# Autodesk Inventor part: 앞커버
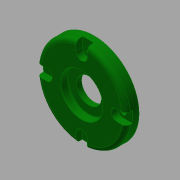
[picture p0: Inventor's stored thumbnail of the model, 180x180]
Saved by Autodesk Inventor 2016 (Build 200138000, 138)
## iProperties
Created: 2019-01
Part Number: 앞커버
Material: 알루미늄 6061
Document SubType Name: Modeling
Designer: mduedu
Density: 2.71 g/cm^3
Appearance: 진녹색
Mass: 65.0159 g
Surface Area: 90.7546 cm^2
Volume: 23.9911 cm^3
Author: mduedu
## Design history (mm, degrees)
sketch "스케치1"
  geometry: L1 (0, 0)-(9, 0); L2 (9, 0)-(9, 32); L3 (9, 32)-(0, 32); L4 (0, 32)-(0, 0); L5 (9, 0)-(12, 0); L6 (12, 0)-(12, 20); L7 (12, 20)-(9, 20); L8 (9, 20)-(9, 0)
  constraints: 16 end point, 4 parallel, 2 horizontal, 2 perpendicular
  dimensions: "d0" = 12 distance between parallel lines of L6 L4; "d2" = 64 diameter of L3 L1; "d3" = 40 diameter of L7 L5; "d4" = 3 distance between parallel lines of L6 L2
revolve "회전1" sketch "스케치1" stored, may be unused: angle "d5" = 90 deg
sketch "스케치2"
  geometry: L1 (0, -32)-(0, 32) reference; L2 (0, 32)-(9, 32) reference; L3 (9, 32)-(9, 20) reference; L4 (9, 20)-(12, 20) reference; L5 (12, 20)-(12, -20) reference; L6 (12, -20)-(9, -20) reference; L7 (9, -20)-(9, -32) reference; L8 (9, -32)-(0, -32) reference; L9 (0, 0)-(5.2, 0); L10 (5.2, 0)-(5.2, 15); L11 (5.2, 15)-(0, 15); L12 (0, 15)-(0, 0); L13 (5.2, 0)-(9, 0); L14 (9, 0)-(9, 9); L15 (9, 9)-(5.2, 9); L16 (5.2, 9)-(5.2, 0); L17 (9, 0)-(12, 0); L18 (12, 0)-(12, 15); L19 (12, 15)-(9, 15); L20 (9, 15)-(9, 0)
  constraints: 24 end point, 6 parallel, 3 horizontal, 3 perpendicular, 1 point on line
  dimensions: "d6" = 3 distance of L18.end L19.end; "d8" = 5.2 distance of L10.end L11.end; "d9" = 30 diameter of L11 L9; "d10" = 18 diameter of L15 L13; "d11" = 30 diameter of L19 L17
revolve "회전2" sketch "스케치2" stored, may be unused: angle "d12" = 90 deg
chamfer "모따기1" distance "d13" = 0.5; stored, may be unused: second distance "d14" = 2, angle "d15" = 30 deg
fillet "모깎기1" dims "d16" = 0.5
fillet "모깎기2" dims "d17" = 3
fillet "모깎기3" dims "d18" = 3
chamfer "모따기2" distance "d24" = 1; stored, may be unused: second distance "d25" = 2, angle "d26" = 45 deg
sketch "스케치3" dims "d19" = 50
  geometry: 6 further points
  constraints: 2 vertical alignment, 1 coincident, 7 other
  dimensions: "d22" = 360 deg dimension on point (0, 0) point (0, 25) (derived)
sketch "스케치4"
  geometry: 4 further points
  constraints: 4 other
hole "구멍1" sketch "스케치4" at (-25, 0), (0, -25), (25, 0), (0, 25) diameter "d27" = 4.5; stored, may be unused: countersink angle "d31" = 90 deg, drill point angle "d33" = 0 deg; dims "d28" = 6, "d29" = 8, "d30" = 4.6, "d32" = 8
sketch "스케치5"
  geometry: L1 (-4, 0)-(-4, 6.749); L2 (4, 0)-(4, 6.749); A1 r 4 centre (0, 0) between (0, 4) and (-4, 0) reference; A2 r 32 centre (0, -25) between (-4, 6.749) and (4, 6.749) reference; A3 r 4 centre (0, 0) between (-4, 0) and (4, 0); A4 r 32 centre (0, -25) between (4, 6.749) and (-4, 6.749); A5 r 4 centre (0, 0) between (4, 0) and (-4, 0); 1 further point
  constraints: 10 point on circle, 4 end point, 3 centre point, 2 coincident, 2 tangent, 1 parallel, 1 vertical
extrude "돌출1" cut sketch "스케치5" stored distance "d34" = 10; taper "d35" = 0 deg
node "솔리드1"
pattern_circular "원형 패턴1" dims angle "d37" = 360 deg
node "절단 모서리 투영1"
